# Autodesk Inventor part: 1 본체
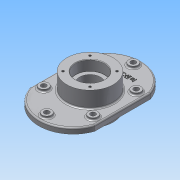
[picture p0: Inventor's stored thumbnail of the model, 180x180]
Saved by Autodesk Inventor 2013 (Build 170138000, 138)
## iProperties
Created: 2015-02
Part Number: 1 본체
Material: 알루미늄 6061
Document SubType Name: Modeling
Designer: ST5
Density: 2.71 g/cm^3
Mass: 1637.14 g
Surface Area: 925.885 cm^2
Volume: 604.109 cm^3
Author: ST5
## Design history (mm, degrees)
sketch "스케치1"
  geometry: L1 (-70, 60)-(70, 60); L2 (70, 60)-(70, -60); L3 (70, -60)-(-70, -60); L4 (-70, -60)-(-70, 60); A1 r 74 centre (0, 36) between (70, 60) and (-70, 60); A2 r 74 centre (0, -36) between (-70, -60) and (70, -60); 5 further points
  constraints: 8 end point, 6 point on circle, 3 vertical alignment, 2 centre point, 2 midpoint, 2 parallel, 1 horizontal, 1 horizontal alignment, 1 perpendicular
  dimensions: "d4" = 140 distance of L2.end L3.end; "d6" = 120 distance of L1.end L2.end; "d8" = 50 distance from line of point (0, 110) L1; "d9" = 50 distance from line of point (0, -110) L3
extrude "돌출1" new body sketch "스케치1" distance "d10" = 12; taper "d11" = 0 deg
sketch "스케치2"
  geometry: C1 r 50 at (0, 0); 1 further point
  constraints: 1 centre point, 1 coincident
  dimensions: "d12" = 100 diameter of C1
extrude "돌출2" join sketch "스케치2" distance "d14" = 35; taper "d15" = 0 deg
sketch "스케치3"
  geometry: C1 r 50 at (0, 0); 1 further point
  constraints: 1 centre point, 1 coincident
  dimensions: "d16" = 100 diameter of C1
extrude "돌출3" join sketch "스케치3" distance "d18" = 23; taper "d19" = 0 deg
sketch "스케치4"
  geometry: L1 (0, 47)-(0, -23); L2 (50, 47)-(-50, 47) reference; L3 (-50, -23)-(50, -23) reference; L4 (31, 47)-(31, 25); L5 (31, 25)-(22.5, 25); L6 (22.5, 25)-(22.5, -1); L7 (22.5, -1)-(31, -1); L8 (31, -1)-(31, -23); 2 further points
  constraints: 12 end point, 3 point on line, 2 collinear, 2 equal length, 2 midpoint, 2 perpendicular, 2 vertical, 1 coincident
  dimensions: "d20" = 62 diameter of L8 L1; "d22" = 45 diameter of L6 L1; "d23" = 22 distance of L4.start L4.end
revolve "회전1" sketch "스케치4" stored, may be unused: angle "d24" = 90 deg
sketch "스케치5"
  geometry: L1 (-70, 60)-(-70, -60) reference; L2 (70, -60)-(70, 60) reference; L3 (53, 56.976)-(53, -56.976); L4 (-53, -56.976)-(-53, 56.976); C1 r 50 at (0, 0) reference; C2 r 10 at (0, 93); C3 r 10 at (0, -93); C4 r 10 at (-53, 46.5); C5 r 10 at (53, 46.5); C6 r 10 at (53, -46.5); C7 r 10 at (-53, -46.5); A1 r 74 centre (0, 36) between (70, 60) and (-70, 60) reference; A2 r 74 centre (0, -36) between (-70, -60) and (70, -60) reference; A3 r 57 centre (0, 36) between (53, 56.976) and (-53, 56.976); A4 r 57 centre (0, -36) between (-53, -56.976) and (53, -56.976)
  constraints: 8 centre point, 6 point on circle, 5 equal radius, 4 end point, 4 point on line, 2 horizontal alignment, 1 vertical alignment, 3 other
  dimensions: "d25" = 17 distance between parallel lines of L1 L4; "d26" = 20 diameter of C2; "d28" = 46.5 vertical distance of C4.centre C2.centre; "d29" = 46.5 vertical distance of C7.centre C3.centre
extrude "돌출4" join sketch "스케치5" distance "d30" = 5; taper "d31" = 0 deg
sketch "스케치6"
  geometry: C1 r 10 at (0, 0) reference; C2 r 10 at (-53, 139.5) reference; C3 r 10 at (0, 93) reference; C4 r 10 at (-53, -46.5) reference; C5 r 10 at (-106, 0) reference; C6 r 10 at (-106, 93) reference; C7 r 5.5 at (-106, 93); C8 r 5.5 at (-53, 139.5); C9 r 5.5 at (0, 93); C10 r 5.5 at (0, 0); C11 r 5.5 at (-53, -46.5); C12 r 5.5 at (-106, 0); 1 further point
  constraints: 6 centre point, 6 coincident, 5 equal radius
  dimensions: "d32" = 11 diameter of C8
extrude "돌출5" cut sketch "스케치6" distance "d34" = 30; taper "d35" = 0 deg
sketch "스케치7"
  geometry: C1 r 31 at (0, 0) reference; C2 r 50 at (0, 0) reference; A1 r 41 centre (0, 0) between (-28.991, 28.991) and (28.991, 28.991); 2 further points
  constraints: 4 point on circle, 2 horizontal alignment, 2 vertical alignment, 1 centre point, 1 coincident
  dimensions: "d36" = 82 diameter of A1; "d38" = 90 deg dimension on C1.centre A1.end A1.start
hole "구멍1" sketch "스케치7" at (28.991, 28.991), (-28.991, 28.991), (-28.991, -28.991), (28.991, -28.991) diameter "d40" = 4.917; stored, may be unused: countersink angle "d44" = 90 deg, drill point angle "d46" = 118 deg; dims "d41" = 10, "d42" = 4, "d43" = 2, "d45" = 13
node "작업 평면1"
chamfer "모따기1" distance "d47" = 1; stored, may be unused: second distance "d48" = 2, angle "d49" = 45 deg
fillet "모깎기1" dims "d50" = 0.3
fillet "모깎기3" dims "d52" = 3
fillet "모깎기4" dims "d53" = 3
fillet "모깎기5" dims "d54" = 3
sketch "스케치8"
  geometry: C1 r 53 at (0, 0) reference; 1 further point
  constraints: 1 vertical alignment, 1 other
  dimensions: "d55" = 65 distance of C1.centre point (0, 65)
feature "엠보싱1" sketch "스케치8" dims "d4" = 140, "d6" = 120, "d8" = 50, "d9" = 50, "d56" = 1, "d57" = 0
node "솔리드1"
mirror "대칭1"
node "투영된 루프1"
node "투영된 루프2"
node "투영된 루프3"
node "투영된 루프4"
node "투영된 루프5"
